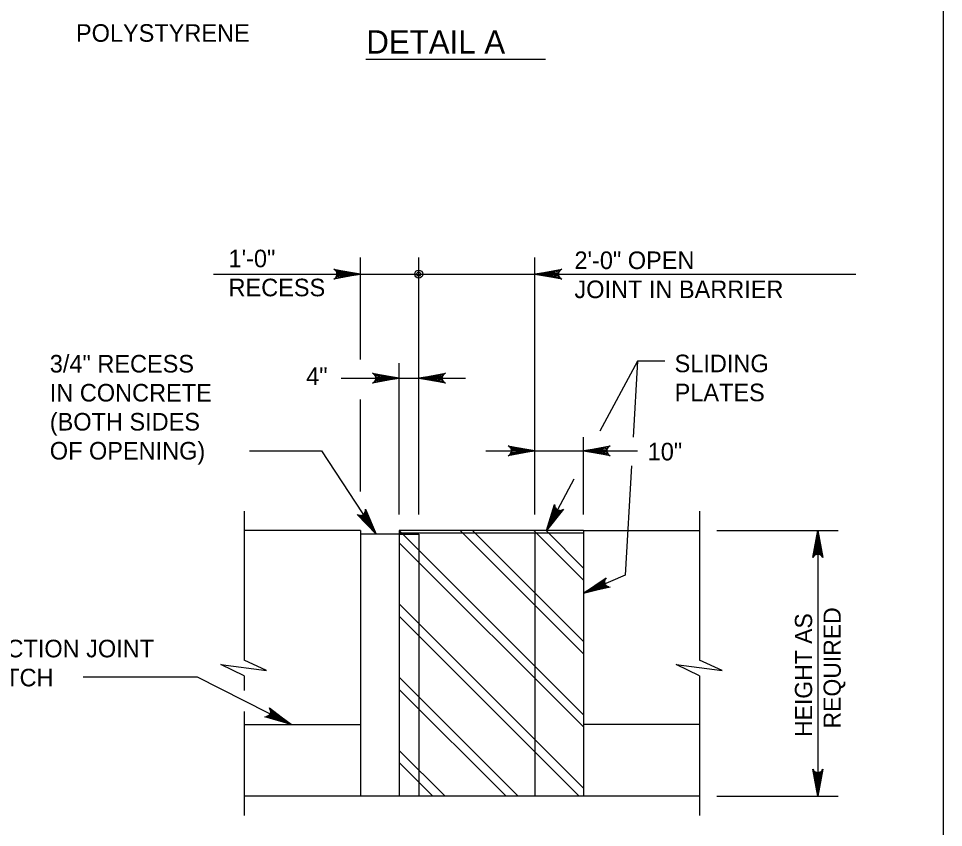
# Model space of a CAD drawing. Extents: x 638167 to 640248, y 296544 to 298920.
# Drawn here: x 639671.1 to 639832.8, y 296851.9 to 296993.3 of the extents above; entities that cross this region are included whole.
import ezdxf

# ---------------------------------------------------------------- set-up
doc = ezdxf.new("R2010")
doc.units = 0
doc.layers.add('1', color=7, linetype='Continuous')
doc.layers.add('57', color=7, linetype='Continuous')

# ---------------------------------------------------------------- blocks, each defined once
blk = doc.blocks.new('DIMDOT')
at = {"layer": '57'}
for radius in [2, 1]:
    blk.add_circle((0, 0), radius, dxfattribs=at)

msp = doc.modelspace()

# ---------------------------------------------------------------- linework, layer by layer
at = {"layer": '1'}
for p, q in [((639832.78, 296559.48), (639832.78, 297123.48)), ((639731.83, 296986.23), (639763.25, 296986.23)), ((639730.91, 296933.73), (639730.91, 296951.55)), ((639741.07, 296906.64), (639741.07, 296951.55)), ((639761.39, 296906.64), (639761.39, 296951.55)), ((639705.23, 296948.63), (639817.46, 296948.63)), ((639779.29, 296933.41), (639772.73, 296921.2)), ((639779.29, 296933.41), (639778.53, 296920.14)), ((639784.06, 296933.41), (639779.29, 296933.41)), ((639737.68, 296906.64), (639737.68, 296933.1)), ((639727.51, 296930.45), (639749.24, 296930.45)), ((639730.91, 296910.62), (639730.91, 296926.74)), ((639769.85, 296906.64), (639769.85, 296920.16)), ((639711.48, 296917.77), (639724.06, 296917.77)), ((639724.06, 296917.77), (639733.61, 296903.17)), ((639752.78, 296917.77), (639779.29, 296917.77)), ((639778.25, 296915.12), (639777.16, 296896.04)), ((639768.2, 296912.77), (639763.38, 296903.8)), ((639710.59, 296907.19), (639710.59, 296881.19)), ((639790.17, 296907.19), (639790.17, 296881.19)), ((639730.91, 296903.8), (639710.59, 296903.8)), ((639730.91, 296903.8), (639730.91, 296857.4)), ((639737.68, 296903.17), (639730.91, 296903.17)), ((639737.68, 296903.8), (639737.68, 296857.4)), ((639769.85, 296903.8), (639737.68, 296903.8)), ((639769.85, 296871.62), (639737.68, 296903.8)), ((639769.85, 296903.38), (639737.68, 296903.38)), ((639737.68, 296903.17), (639741.07, 296903.17)), ((639741.07, 296903.17), (639741.07, 296857.4)), ((639769.85, 296882.29), (639748.34, 296903.8)), ((639769.85, 296884.42), (639750.47, 296903.8)), ((639769.85, 296895.14), (639761.18, 296903.8)), ((639761.39, 296903.38), (639761.39, 296857.4)), ((639763.32, 296903.8), (639769.85, 296897.27)), ((639769.85, 296903.8), (639769.85, 296857.4)), ((639769.85, 296903.8), (639790.17, 296903.8)), ((639793.16, 296903.8), (639814.36, 296903.8)), ((639810.82, 296903.8), (639810.82, 296857.4)), ((639769.85, 296869.49), (639737.68, 296901.66)), ((639777.16, 296896.04), (639769.85, 296892.86)), ((639769.85, 296858.82), (639737.68, 296891)), ((639769.14, 296857.4), (639737.68, 296888.86)), ((639682.44, 296878.28), (639702.33, 296878.28)), ((639702.33, 296878.28), (639718.76, 296869.94)), ((639710.59, 296878.42), (639710.59, 296875.89)), ((639790.17, 296878.42), (639790.17, 296854.01)), ((639758.48, 296857.4), (639737.68, 296878.2)), ((639756.34, 296857.4), (639737.68, 296876.06)), ((639710.59, 296872.18), (639710.59, 296854.01)), ((639710.59, 296869.94), (639730.91, 296869.94)), ((639790.17, 296869.94), (639769.85, 296869.94)), ((639745.67, 296857.4), (639737.68, 296865.39)), ((639743.54, 296857.4), (639737.68, 296863.26)), ((639790.17, 296857.4), (639710.59, 296857.4)), ((639793.16, 296857.4), (639814.36, 296857.4))]:
    msp.add_line(p, q, dxfattribs=at)
for points in [[(639730.91, 296948.63), (639726.21, 296947.75), (639726.39, 296947.88), (639726.57, 296948), (639726.66, 296948.16), (639726.76, 296948.32), (639726.78, 296948.47), (639726.81, 296948.63), (639726.78, 296948.79), (639726.76, 296948.95), (639726.66, 296949.1), (639726.57, 296949.26), (639726.39, 296949.39), (639726.21, 296949.51), (639730.91, 296948.63), (639726.39, 296949.39), (639726.57, 296949.26), (639730.91, 296948.63), (639726.66, 296949.1), (639726.76, 296948.95), (639730.91, 296948.63), (639726.78, 296948.79), (639726.81, 296948.63), (639730.91, 296948.63), (639726.78, 296948.47), (639726.76, 296948.32), (639730.91, 296948.63), (639726.66, 296948.16), (639726.57, 296948), (639730.91, 296948.63), (639726.39, 296947.88)], [(639761.39, 296948.63), (639766.08, 296949.51), (639765.9, 296949.39), (639765.72, 296949.26), (639765.63, 296949.1), (639765.54, 296948.95), (639765.51, 296948.79), (639765.48, 296948.63), (639765.51, 296948.47), (639765.54, 296948.32), (639765.63, 296948.16), (639765.72, 296948), (639765.9, 296947.88), (639766.08, 296947.75), (639761.39, 296948.63), (639765.9, 296947.88), (639765.72, 296948), (639761.39, 296948.63), (639765.63, 296948.16), (639765.54, 296948.32), (639761.39, 296948.63), (639765.51, 296948.47), (639765.48, 296948.63), (639761.39, 296948.63), (639765.51, 296948.79), (639765.54, 296948.95), (639761.39, 296948.63), (639765.63, 296949.1), (639765.72, 296949.26), (639761.39, 296948.63), (639765.9, 296949.39)], [(639737.68, 296930.45), (639732.98, 296929.57), (639733.16, 296929.69), (639733.34, 296929.82), (639733.44, 296929.98), (639733.53, 296930.13), (639733.56, 296930.29), (639733.58, 296930.45), (639733.56, 296930.61), (639733.53, 296930.76), (639733.44, 296930.92), (639733.34, 296931.08), (639733.16, 296931.2), (639732.98, 296931.33), (639737.68, 296930.45), (639733.16, 296931.2), (639733.34, 296931.08), (639737.68, 296930.45), (639733.44, 296930.92), (639733.53, 296930.76), (639737.68, 296930.45), (639733.56, 296930.61), (639733.58, 296930.45), (639737.68, 296930.45), (639733.56, 296930.29), (639733.53, 296930.13), (639737.68, 296930.45), (639733.44, 296929.98), (639733.34, 296929.82), (639737.68, 296930.45), (639733.16, 296929.69)], [(639741.07, 296930.45), (639745.76, 296931.33), (639745.58, 296931.2), (639745.4, 296931.08), (639745.31, 296930.92), (639745.22, 296930.76), (639745.19, 296930.61), (639745.16, 296930.45), (639745.19, 296930.29), (639745.22, 296930.13), (639745.31, 296929.98), (639745.4, 296929.82), (639745.58, 296929.69), (639745.76, 296929.57), (639741.07, 296930.45), (639745.58, 296929.69), (639745.4, 296929.82), (639741.07, 296930.45), (639745.31, 296929.98), (639745.22, 296930.13), (639741.07, 296930.45), (639745.19, 296930.29), (639745.16, 296930.45), (639741.07, 296930.45), (639745.19, 296930.61), (639745.22, 296930.76), (639741.07, 296930.45), (639745.31, 296930.92), (639745.4, 296931.08), (639741.07, 296930.45), (639745.58, 296931.2)], [(639761.39, 296917.77), (639756.69, 296916.89), (639756.87, 296917.02), (639757.05, 296917.14), (639757.14, 296917.3), (639757.24, 296917.46), (639757.26, 296917.61), (639757.29, 296917.77), (639757.26, 296917.93), (639757.24, 296918.09), (639757.14, 296918.24), (639757.05, 296918.4), (639756.87, 296918.53), (639756.69, 296918.65), (639761.39, 296917.77), (639756.87, 296918.53), (639757.05, 296918.4), (639761.39, 296917.77), (639757.14, 296918.24), (639757.24, 296918.09), (639761.39, 296917.77), (639757.26, 296917.93), (639757.29, 296917.77), (639761.39, 296917.77), (639757.26, 296917.61), (639757.24, 296917.46), (639761.39, 296917.77), (639757.14, 296917.3), (639757.05, 296917.14), (639761.39, 296917.77), (639756.87, 296917.02)], [(639769.85, 296917.77), (639774.55, 296918.65), (639774.37, 296918.53), (639774.19, 296918.4), (639774.1, 296918.24), (639774, 296918.09), (639773.97, 296917.93), (639773.95, 296917.77), (639773.97, 296917.61), (639774, 296917.46), (639774.1, 296917.3), (639774.19, 296917.14), (639774.37, 296917.02), (639774.55, 296916.89), (639769.85, 296917.77), (639774.37, 296917.02), (639774.19, 296917.14), (639769.85, 296917.77), (639774.1, 296917.3), (639774, 296917.46), (639769.85, 296917.77), (639773.97, 296917.61), (639773.95, 296917.77), (639769.85, 296917.77), (639773.97, 296917.93), (639774, 296918.09), (639769.85, 296917.77), (639774.1, 296918.24), (639774.19, 296918.4), (639769.85, 296917.77), (639774.37, 296918.53)], [(639733.61, 296903.17), (639730.3, 296906.62), (639730.51, 296906.54), (639730.71, 296906.45), (639730.89, 296906.46), (639731.08, 296906.47), (639731.22, 296906.53), (639731.37, 296906.6), (639731.49, 296906.71), (639731.6, 296906.81), (639731.68, 296906.98), (639731.76, 296907.14), (639731.77, 296907.36), (639731.78, 296907.58), (639733.61, 296903.17), (639731.77, 296907.36), (639731.76, 296907.14), (639733.61, 296903.17), (639731.68, 296906.98), (639731.6, 296906.81), (639733.61, 296903.17), (639731.49, 296906.71), (639731.37, 296906.6), (639733.61, 296903.17), (639731.22, 296906.53), (639731.08, 296906.47), (639733.61, 296903.17), (639730.89, 296906.46), (639730.71, 296906.45), (639733.61, 296903.17), (639730.51, 296906.54)], [(639763.38, 296903.8), (639764.83, 296908.36), (639764.85, 296908.14), (639764.88, 296907.92), (639764.97, 296907.77), (639765.07, 296907.61), (639765.19, 296907.51), (639765.32, 296907.41), (639765.47, 296907.36), (639765.62, 296907.31), (639765.8, 296907.32), (639765.99, 296907.33), (639766.18, 296907.43), (639766.38, 296907.53), (639763.38, 296903.8), (639766.18, 296907.43), (639765.99, 296907.33), (639763.38, 296903.8), (639765.8, 296907.32), (639765.62, 296907.31), (639763.38, 296903.8), (639765.47, 296907.36), (639765.32, 296907.41), (639763.38, 296903.8), (639765.19, 296907.51), (639765.07, 296907.61), (639763.38, 296903.8), (639764.97, 296907.77), (639764.88, 296907.92), (639763.38, 296903.8), (639764.85, 296908.14)], [(639810.82, 296903.8), (639811.7, 296899.11), (639811.58, 296899.29), (639811.45, 296899.47), (639811.29, 296899.56), (639811.14, 296899.66), (639810.98, 296899.68), (639810.82, 296899.71), (639810.66, 296899.68), (639810.51, 296899.66), (639810.35, 296899.56), (639810.19, 296899.47), (639810.07, 296899.29), (639809.94, 296899.11), (639810.82, 296903.8), (639810.07, 296899.29), (639810.19, 296899.47), (639810.82, 296903.8), (639810.35, 296899.56), (639810.51, 296899.66), (639810.82, 296903.8), (639810.66, 296899.68), (639810.82, 296899.71), (639810.82, 296903.8), (639810.98, 296899.68), (639811.14, 296899.66), (639810.82, 296903.8), (639811.29, 296899.56), (639811.45, 296899.47), (639810.82, 296903.8), (639811.58, 296899.29)], [(639769.85, 296892.86), (639773.81, 296895.54), (639773.69, 296895.35), (639773.58, 296895.16), (639773.55, 296894.98), (639773.53, 296894.8), (639773.57, 296894.64), (639773.61, 296894.49), (639773.7, 296894.36), (639773.78, 296894.22), (639773.93, 296894.12), (639774.08, 296894.01), (639774.3, 296893.97), (639774.51, 296893.92), (639769.85, 296892.86), (639774.3, 296893.97), (639774.08, 296894.01), (639769.85, 296892.86), (639773.93, 296894.12), (639773.78, 296894.22), (639769.85, 296892.86), (639773.7, 296894.36), (639773.61, 296894.49), (639769.85, 296892.86), (639773.57, 296894.64), (639773.53, 296894.8), (639769.85, 296892.86), (639773.55, 296894.98), (639773.58, 296895.16), (639769.85, 296892.86), (639773.69, 296895.35)], [(639710.59, 296878.42), (639706.5, 296880.42), (639714.49, 296879.33), (639710.59, 296881.19)], [(639790.17, 296878.42), (639786.09, 296880.42), (639794.08, 296879.33), (639790.17, 296881.19)], [(639718.76, 296869.94), (639714.17, 296871.28), (639714.39, 296871.31), (639714.61, 296871.34), (639714.76, 296871.44), (639714.92, 296871.53), (639715.01, 296871.66), (639715.11, 296871.79), (639715.16, 296871.94), (639715.2, 296872.1), (639715.19, 296872.28), (639715.18, 296872.46), (639715.07, 296872.66), (639714.97, 296872.85), (639718.76, 296869.94), (639715.07, 296872.66), (639715.18, 296872.46), (639718.76, 296869.94), (639715.19, 296872.28), (639715.2, 296872.1), (639718.76, 296869.94), (639715.16, 296871.94), (639715.11, 296871.79), (639718.76, 296869.94), (639715.01, 296871.66), (639714.92, 296871.53), (639718.76, 296869.94), (639714.76, 296871.44), (639714.61, 296871.34), (639718.76, 296869.94), (639714.39, 296871.31)], [(639810.82, 296857.4), (639809.94, 296862.1), (639810.07, 296861.92), (639810.19, 296861.73), (639810.35, 296861.64), (639810.51, 296861.55), (639810.66, 296861.52), (639810.82, 296861.49), (639810.98, 296861.52), (639811.14, 296861.55), (639811.29, 296861.64), (639811.45, 296861.73), (639811.58, 296861.92), (639811.7, 296862.1), (639810.82, 296857.4), (639811.58, 296861.92), (639811.45, 296861.73), (639810.82, 296857.4), (639811.29, 296861.64), (639811.14, 296861.55), (639810.82, 296857.4), (639810.98, 296861.52), (639810.82, 296861.49), (639810.82, 296857.4), (639810.66, 296861.52), (639810.51, 296861.55), (639810.82, 296857.4), (639810.35, 296861.64), (639810.19, 296861.73), (639810.82, 296857.4), (639810.07, 296861.92)]]:
    msp.add_lwpolyline(points, dxfattribs=at)

# ---------------------------------------------------------------- block references
at = {"layer": '1', "xscale": 0.349999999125, "yscale": 0.349999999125}
msp.add_blockref('DIMDOT', (639741.07, 296948.63), dxfattribs=at)

# ---------------------------------------------------------------- texts
at = {"layer": '1'}
for s, height, p in [('POLYSTYRENE', 3.072, (639681.17, 296989.24)), ('DETAIL A', 4.08, (639731.92, 296987.18)), ('3/4" RECESS', 3.072, (639676.6, 296931.44)), ('4"', 3.072, (639721.4, 296929.25)), ('IN CONCRETE', 3.072, (639676.6, 296926.37)), ('(BOTH SIDES', 3.072, (639676.6, 296921.3)), ('OF OPENING)', 3.072, (639676.6, 296916.23)), ('10"', 3.072, (639781.09, 296916.08)), ('CONSTRUCTION JOINT', 3.072, (639648.72, 296881.66)), ('AND V-NOTCH', 3.072, (639648.72, 296876.59))]:
    msp.add_text(s, height=height, dxfattribs=at).set_placement(p)
for s, height, rotation, p in [('1\'-0"', 3.072, 360, (639707.84, 296949.83)), ('2\'-0" OPEN', 3.072, 360, (639768.29, 296949.52)), ('RECESS', 3.072, 360, (639707.84, 296944.76)), ('JOINT IN BARRIER', 3.072, 360, (639768.29, 296944.44)), ('SLIDING', 3.072, 360, (639785.79, 296931.49)), ('PLATES', 3.072, 360, (639785.79, 296926.42)), ('REQUIRED', 3, 90, (639814.82, 296869.23)), ('HEIGHT AS', 3, 90, (639809.82, 296867.74))]:
    msp.add_text(s, height=height, rotation=rotation, dxfattribs=at).set_placement(p)

doc.saveas('drawing.dxf')
